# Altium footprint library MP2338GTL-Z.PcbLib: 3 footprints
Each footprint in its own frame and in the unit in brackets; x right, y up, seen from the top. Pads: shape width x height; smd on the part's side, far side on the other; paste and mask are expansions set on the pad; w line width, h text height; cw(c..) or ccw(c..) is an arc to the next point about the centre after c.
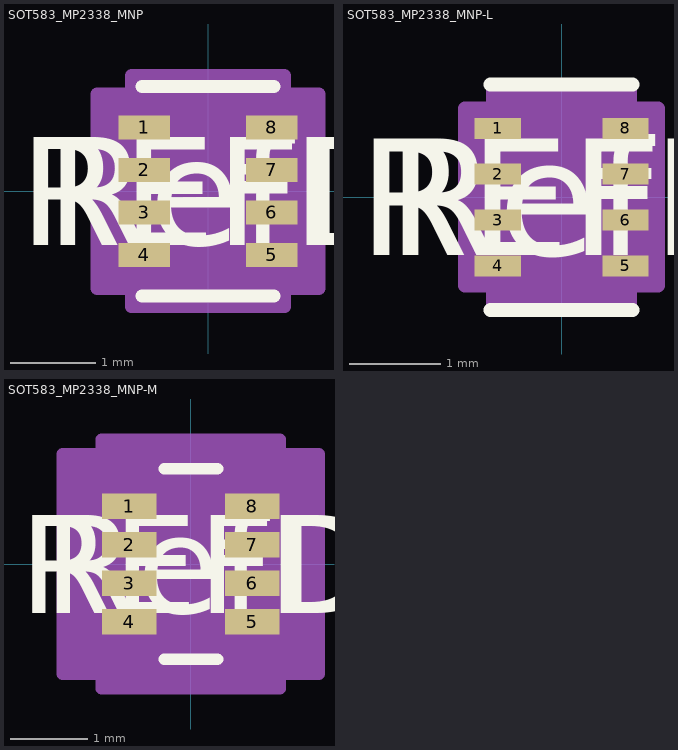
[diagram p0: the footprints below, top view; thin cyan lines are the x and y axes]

## SOT583_MP2338_MNP [mm]
pads (8):
  rect 0.606x0.279 smd paste+0 mask+0: 1(-0.748,0.75) 2(-0.748,0.25) 3(-0.748,-0.25) 4(-0.748,-0.75) 5(0.748,-0.75) 6(0.748,-0.25) 7(0.748,0.25) 8(0.748,0.75)
Top Overlay:
  lines w0.152: -0.775,-1.232 0.775,-1.232 ; -0.775,1.232 0.775,1.232
  text "RefDes" at -1.905,-0.635 h1.27
  text "REFDES" at -2.222,-0.635 h1.27
Mechanical 13:
  circle w0: c-0.445,0.75 r0.076
  lines w0: -0.305,1.105 ccw(c0,1.105) 0.305,1.105
  lines w0.025: -0.648,-1.105 0.648,-1.105 0.648,1.105 -0.648,1.105 -0.648,-1.105
  text "RefDes2" at -2.222,-0.635 h1.27
Mechanical 15:
  region: 0.902,-1.359 -0.902,-1.359 -0.902,-1.144 -1.305,-1.144 -1.305,1.144 -0.902,1.144 -0.902,1.359 0.902,1.359 0.902,1.144 1.305,1.144 1.305,-1.144 0.902,-1.144
  lines w0.152: -1.305,-1.144 -0.902,-1.144 -0.902,-1.359 0.902,-1.359 0.902,-1.144 1.305,-1.144 1.305,1.144 0.902,1.144 0.902,1.359 -0.902,1.359 -0.902,1.144 -1.305,1.144 -1.305,-1.144
3D body "SOT583_MP2338_MNP.step": height 0.56, standoff 0, extent -0.851,-1.105 0.851,1.105

## SOT583_MP2338_MNP-L [mm]
pads (8):
  rect 0.506x0.229 smd paste+0 mask+0: 1(-0.698,0.75) 2(-0.698,0.25) 3(-0.698,-0.25) 4(-0.698,-0.75) 5(0.698,-0.75) 6(0.698,-0.25) 7(0.698,0.25) 8(0.698,0.75)
Top Overlay:
  lines w0.152: -0.775,-1.232 0.775,-1.232 ; -0.775,1.232 0.775,1.232
  text "RefDes" at -1.905,-0.635 h1.27
  text "REFDES" at -2.222,-0.635 h1.27
Mechanical 13:
  circle w0: c-0.445,0.75 r0.076
  lines w0: -0.305,1.105 ccw(c0,1.105) 0.305,1.105
  lines w0.025: -0.648,-1.105 0.648,-1.105 0.648,1.105 -0.648,1.105 -0.648,-1.105
  text "RefDes2" at -2.222,-0.635 h1.27
Mechanical 15:
  region: 0.749,-1.206 -0.749,-1.206 -0.749,-0.966 -1.052,-0.966 -1.052,0.966 -0.749,0.966 -0.749,1.206 0.749,1.206 0.749,0.966 1.052,0.966 1.052,-0.966 0.749,-0.966
  lines w0.152: -1.052,-0.966 -0.749,-0.966 -0.749,-1.206 0.749,-1.206 0.749,-0.966 1.052,-0.966 1.052,0.966 0.749,0.966 0.749,1.206 -0.749,1.206 -0.749,0.966 -1.052,0.966 -1.052,-0.966
3D body "SOT583_MP2338_MNP.step": height 0.56, standoff 0, extent -0.851,-1.105 0.851,1.105

## SOT583_MP2338_MNP-M [mm]
pads (8):
  rect 0.706x0.329 smd paste+0 mask+0: 1(-0.798,0.75) 2(-0.798,0.25) 3(-0.798,-0.25) 4(-0.798,-0.75) 5(0.798,-0.75) 6(0.798,-0.25) 7(0.798,0.25) 8(0.798,0.75)
Top Overlay:
  lines w0.152: -0.344,-1.232 0.344,-1.232 ; -0.344,1.232 0.344,1.232
  text "RefDes" at -1.905,-0.635 h1.27
  text "REFDES" at -2.222,-0.635 h1.27
Mechanical 13:
  circle w0: c-0.445,0.75 r0.076
  lines w0: -0.305,1.105 ccw(c0,1.105) 0.305,1.105
  lines w0.025: -0.648,-1.105 0.648,-1.105 0.648,1.105 -0.648,1.105 -0.648,-1.105
  text "RefDes2" at -2.222,-0.635 h1.27
Mechanical 15:
  region: 1.156,-1.613 -1.156,-1.613 -1.156,-1.423 -1.659,-1.423 -1.659,1.423 -1.156,1.423 -1.156,1.613 1.156,1.613 1.156,1.423 1.659,1.423 1.659,-1.423 1.156,-1.423
  lines w0.152: -1.659,-1.423 -1.156,-1.423 -1.156,-1.613 1.156,-1.613 1.156,-1.423 1.659,-1.423 1.659,1.423 1.156,1.423 1.156,1.613 -1.156,1.613 -1.156,1.423 -1.659,1.423 -1.659,-1.423
3D body "SOT583_MP2338_MNP.step": height 0.56, standoff 0, extent -0.851,-1.105 0.851,1.105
